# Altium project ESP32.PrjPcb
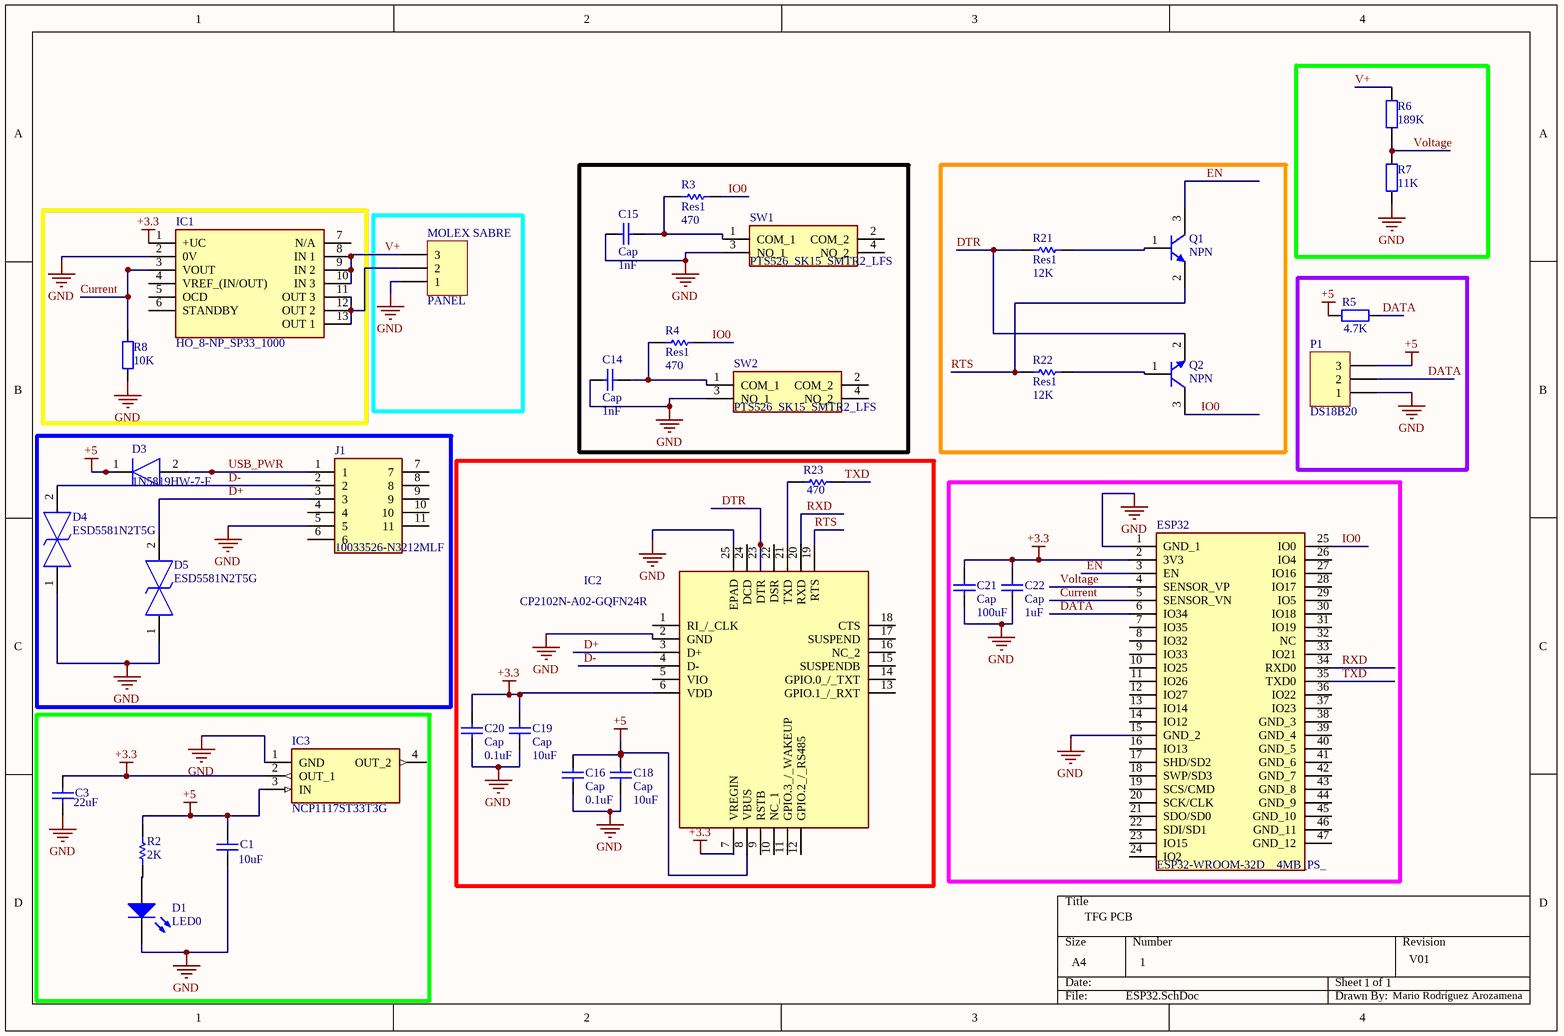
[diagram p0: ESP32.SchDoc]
1 sheet, 35 parts. Net scope: global (net labels, ports and power ports of the same name join across sheets).
Board file: ESP32.PcbDoc

## Sheet ESP32.SchDoc
size A4

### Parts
C1  value 10uF  [6-0805_M]  (hidden comment: Cap)
C3  value 22uF  [6-0805_M]  (hidden comment: Cap)
C14  Cap  value 1nF  [6-0805_M]
C15  Cap  value 1nF  [6-0805_M]
C16  Cap  value 0.1uF  [6-0805_M]
C18  Cap  value 10uF  [6-0805_M]
C19  Cap  value 10uF  [6-0805_M]
C20  Cap  value 0.1uF  [6-0805_M]
C21  Cap  value 100uF  [6-0805_M]
C22  Cap  value 1uF  [6-0805_M]
D1  LED0  [6-0805_M]
D3  1N5819HW-7-F  [SOD3716X145N]
D4  ESD5581N2T5G  [ESD5581N2T5G]
D5  ESD5581N2T5G  [ESD5581N2T5G]
ESP32  ESP32-WROOM-32D__4MB_PS_  [ESP32WROOM32D4MBPS]
IC1  HO_8-NP_SP33_1000  [HO8NPSP33-1000]
IC2  CP2102N-A02-GQFN24R  [QFN50P400X400X80-25N-D]
IC3  NCP1117ST33T3G  [SOT230P700X180-4N]
J1  10033526-N3212MLF  [10033526N3212MLF]
MOLEX_SABRE  PANEL  [43160-4303]
P1  DS18B20  [43650-0315]
Q1  NPN  [SOT-23_M]
Q2  NPN  [SOT-23_M]
R2  value 2K  [6-0805_M]  (hidden comment: Res1)
R3  Res1  value 470  [6-0805_M]
R4  Res1  value 470  [6-0805_M]
R5  value 4.7K  [6-0805_M]  (hidden comment: Res2)
R6  value 189K  [6-0805_M]  (hidden comment: Res2)
R7  value 11K  [6-0805_M]  (hidden comment: Res2)
R8  value 10K  [6-0805_M]  (hidden comment: Res2)
R21  Res1  value 12K  [6-0805_M]
R22  Res1  value 12K  [6-0805_M]
R23  value 470  [6-0805_M]  (hidden comment: Res1)
SW1  PTS526_SK15_SMTR2_LFS  [PTS526SK15SMTR2LFS]
SW2  PTS526_SK15_SMTR2_LFS  [PTS526SK15SMTR2LFS]

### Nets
+3.3: C3.2 C19.2 C20.2 C21.2 C22.2 ESP32.2(3V3) IC1.1(+UC) IC2.6(VDD) IC2.7(VREGIN) IC3.2(OUT_1)
+5: C1.2 C16.2 C18.2 D3.1(K) IC2.8(VBUS) IC3.3(IN) P1.3 R2.2 R5.1
GND: C1.1 C3.1 C14.1 C15.1 C16.1 C18.1 C19.1 C20.1 C21.1 C22.1 D1.2(K) D4.1 D5.1 ESP32.1(GND_1) ESP32.15(GND_2) IC1.2(0V) IC2.2(GND) IC2.25(EPAD) IC3.1(GND) J1.5 MOLEX_SABRE.1 P1.1 R7.1 R8.1 SW1.3(NO_1) SW2.3(NO_1)
Current: ESP32.5(SENSOR_VN) IC1.3(VOUT) R8.2
D+: D5.2 IC2.3(D+) J1.3
D-: D4.2 IC2.4(D-) J1.2
DATA: ESP32.6(IO34) P1.2 R5.2
DTR: IC2.23(DTR) Q2.2(E) R21.1
EN: ESP32.3(EN) Q1.3(C)
IO0: ESP32.25(IO0) Q2.3(C) R3.2 R4.2
RTS: IC2.19(RTS) Q1.2(E) R22.1
RXD: ESP32.34(RXD0) IC2.20(RXD)
TXD: ESP32.35(TXD0) R23.2
USB_PWR: D3.2(A) J1.1
V+: IC1.8(IN_1) IC1.9(IN_2) IC1.10(IN_3) MOLEX_SABRE.3 R6.2
Voltage: ESP32.4(SENSOR_VP) R6.1 R7.2
NetC14_2: C14.2 R4.1 SW2.1(COM_1)
NetC15_2: C15.2 R3.1 SW1.1(COM_1)
NetD1_1: D1.1(A) R2.1
NetIC1_11: IC1.11(OUT_3) IC1.12(OUT_2) IC1.13(OUT_1) MOLEX_SABRE.2
NetIC2_21: IC2.21(TXD) R23.1
NetQ1_1: Q1.1(B) R21.2
NetQ2_1: Q2.1(B) R22.2

Not connected (* = marked no-connect by the designer): ESP32 7(IO35) 8(IO32) 9(IO33) 10(IO25) 11(IO26) 12(IO27) 13(IO14) 14(IO12) 16(IO13) 17(SHD/SD2) 18(SWP/SD3) 19(SCS/CMD) 20(SCK/CLK) 21(SDO/SD0) 22(SDI/SD1) 23(IO15) 24(IO2) 26(IO4) 27(IO16) 28(IO17) 29(IO5) 30(IO18) 31(IO19) 32(NC) 33(IO21) 36(IO22) 37(IO23) 38(GND_3) 39(GND_4) 40(GND_5) 41(GND_6) 42(GND_7) 43(GND_8) 44(GND_9) 45(GND_10) 46(GND_11) 47(GND_12); IC1 4(VREF_(IN/OUT)) 5(OCD) 6(STANDBY) 7(N/A); IC2 1(RI_/_CLK) 5(VIO) 9(RSTB) 10(NC_1) 11(GPIO.3_/_WAKEUP) 12(GPIO.2_/_RS485) 13(GPIO.1_/_RXT) 14(GPIO.0_/_TXT) 15(SUSPENDB) 16(NC_2) 17(SUSPEND) 18(CTS) 22(DSR) 24(DCD); IC3 4(OUT_2); J1 4 6 7 8 9 10 11; SW1 2(COM_2) 4(NO_2); SW2 2(COM_2) 4(NO_2)

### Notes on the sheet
- TFG PCB
- 1
- V01
- Mario Rodríguez Arozamena

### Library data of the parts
C1 C3 C14-C16 C18-C22 = Cap: Capacitor
D1 = LED0: Typical INFRARED GaAs LED
D3 = 1N5819HW-7-F: Diode; Manufacturer_Name: Diodes Inc.
D4 D5 = ESD5581N2T5G: TVS Diode (Bi-directional); Manufacturer_Name: ON Semiconductor
ESP32 = ESP32-WROOM-32D__4MB_PS_: Integrated Circuit; Manufacturer_Name: Espressif Systems; Manufacturer_Part_Number: ESP32-WROOM-32D (4MB PS)
IC1 = HO_8-NP_SP33_1000: Integrated Circuit; Manufacturer_Name: LEM; Manufacturer_Part_Number: HO 10-P/SP33
IC2 = CP2102N-A02-GQFN24R: Integrated Circuit; Manufacturer_Name: Silicon Labs
IC3 = NCP1117ST33T3G: Integrated Circuit; Manufacturer_Name: ON Semiconductor
J1 = 10033526-N3212MLF: Connector; Manufacturer_Name: Amphenol
MOLEX_SABRE = Molex SABRE 3pin vertical: Molex SABRE 3pin vertical connector
P1 = Header 3: Header, 3-Pin
Q1 Q2 = NPN: NPN Bipolar Transistor
R2-R4 R21-R23 = Res1: Resistor
R5-R8 = Res2: Resistor
SW1 SW2 = PTS526_SK15_SMTR2_LFS: Switch; Manufacturer_Name: C & K COMPONENTS; Manufacturer_Part_Number: PTS526 SK15 SMTR2 LFS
